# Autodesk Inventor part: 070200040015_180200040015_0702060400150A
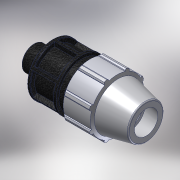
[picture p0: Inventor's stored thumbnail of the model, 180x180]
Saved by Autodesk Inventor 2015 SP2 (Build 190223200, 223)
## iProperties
Created: 2017-02
Part Number: 070200040015_180200040015_0702060400150A
Material: PVC-Piping
Description: PLASSON MALE ADAPTOR 40-1.1/2"
Document SubType Name: Modeling
Designer: KIM
Mass: 92.6774 g
Surface Area: 199.44 cm^2
Volume: 66.1981 cm^3
Density: 1.4 g/cm^3
Appearance: PTFE
Author: KIM
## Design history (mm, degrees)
derived "07020.ipt"
feature "Solid1::07020.ipt"
tag "TaggingFeature1"
body "Solid1"
other parameters: "d4" = 16.71429, "d5" = 29.25, "d7" = 82, "d8" = 61.5, "d9" = 16.71429, "d11" = 3.34286, "d12" = 65.6, "d13" = 120 deg, "d15" = 8 deg, "d16" = 73.8, "d18" = 2, "d19" = 35 deg, "d20" = 17.5 deg, "d21" = 76.26, "d23" = 0, "d25" = 360 deg, "d27" = 1.64, "d34" = 4.1, "d36" = 0, "d42" = 29.25, "d43" = 2.46, "d46" = 1.2, "d51" = 117, "d52" = 22, "d53" = 0.8, "d55" = 360 deg, "d57" = 47.803, "d58" = 33.4621, "d59" = 23.4, "E_" = 82, "H_" = 117, "l_2" = 22, "R_" = 47.803
